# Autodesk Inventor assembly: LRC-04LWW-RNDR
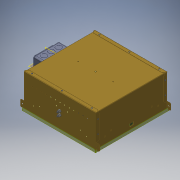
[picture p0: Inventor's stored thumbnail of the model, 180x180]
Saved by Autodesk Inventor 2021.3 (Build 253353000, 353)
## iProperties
Part Number: LRC-04LWW-RNDR
Document SubType Name: Assembly
Designer: JChurch
Author: JChurch
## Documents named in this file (5)
- X:\Revit Files\0000-Un-Zipped\COB\LRC-04LWW-RND\LRC-04LWW-RNDR.iam
- X:\INVENTOR\830\830520-00-00.ipt
- X:\INVENTOR\881\881088-00-00.iam
- X:\INVENTOR\750\750460-00-XX.iam
- X:\INVENTOR\725\725377-01-00.ipt
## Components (4 placed, 4 different names)
1. 830520-00-00:1 — Mate:1, Mate:2, Mate:3, Mate:4, Tangent:1, Angle:1, Insert:1
2. 881088-00-00:1 [sub-assembly] — Mate:4, Tangent:1, Angle:1
3. 750460-00-XX:1 [sub-assembly] — Insert:1, Flush:1, Mate:5, Mate:6
4. 725377-01-00:1 — Mate:5, Mate:6
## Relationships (10: Mate 6, Tangent 1, Angle 1, Insert 1, Flush 1)
- Mate:1: 830520-00-00:1
- Mate:2: 830520-00-00:1
- Mate:3: 830520-00-00:1
- Mate:4: 830520-00-00:1 ↔ 881088-00-00:1
- Tangent:1: 830520-00-00:1 ↔ 881088-00-00:1
- Angle:1: 830520-00-00:1 ↔ 881088-00-00:1
- Insert:1: 830520-00-00:1 ↔ 750460-00-XX:1
- Flush:1: 750460-00-XX:1
- Mate:5: 750460-00-XX:1 ↔ 725377-01-00:1
- Mate:6: 750460-00-XX:1 ↔ 725377-01-00:1
